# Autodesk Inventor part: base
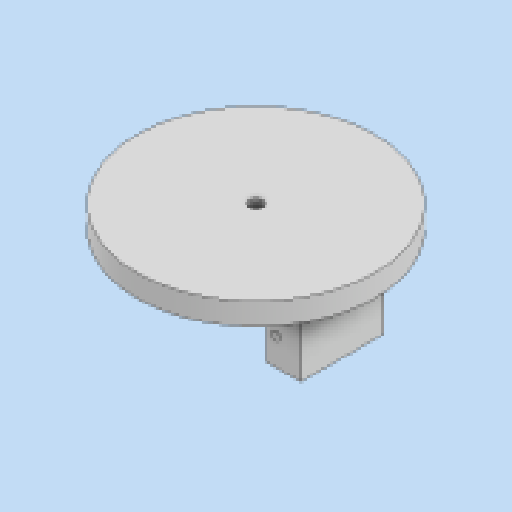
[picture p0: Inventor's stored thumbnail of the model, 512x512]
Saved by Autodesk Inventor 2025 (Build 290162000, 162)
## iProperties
Created: 2026-03
Part Number: base
Material: Generico
Document SubType Name: Modeling
Designer: Ryzen5700u
Density: 1 g/cm^3
Appearance: Default
Author: Ryzen5700u
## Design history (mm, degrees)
sketch "Schizzo1"
  geometry: L1 (11.5, -6.25)-(11.5, 6.25) reference; L2 (11.5, -6.25)-(16.1, -6.25) reference; L3 (16.1, -6.25)-(16.1, -0.6) reference; L4 (16.1, -0.6)-(14.7, -0.6) reference; L5 (14.7, 0.6)-(16.1, 0.6) reference; L6 (16.1, 0.6)-(16.1, 6.25) reference; L7 (11.5, 6.25)-(16.1, 6.25) reference; L8 (-11.5, 6.25)-(-11.5, -6.25) reference; L9 (-11.5, 6.25)-(-16.1, 6.25) reference; L10 (-16.1, 6.25)-(-16.1, 0.6) reference; L11 (-16.1, 0.6)-(-14.7, 0.6) reference; L12 (-14.7, -0.6)-(-16.1, -0.6) reference; L13 (-16.1, -0.6)-(-16.1, -6.25) reference; L14 (-11.5, -6.25)-(-16.1, -6.25) reference; L15 (11.5, -6.25)-(19.5, -6.25); L16 (19.5, -6.25)-(19.5, 6.25); L17 (19.5, 6.25)-(11.5, 6.25); L18 (11.5, 6.25)-(11.5, -6.25); L19 (-11.5, -6.25)-(-19.5, -6.25); L20 (-19.5, -6.25)-(-19.5, 6.25); L21 (-19.5, 6.25)-(-11.5, 6.25); L22 (-11.5, 6.25)-(-11.5, -6.25); C1 r 1 at (13.9, 0); A1 r 1 centre (13.9, 0) between (14.7, 0.6) and (14.7, -0.6) reference; A2 r 1 centre (-13.9, 0) between (-14.7, -0.6) and (-14.7, 0.6) reference; 9 further points
  constraints: 16 end point, 4 parallel, 2 coincident, 2 horizontal, 2 perpendicular, 1 centre point, 1 point on line, 3 other
  dimensions: "d0" = 8 distance of L17.end L16.end; "d1" = 8 distance of L20.end L21.end
  node "Riferimento1"
  node "Riferimento2"
node "Piano di lavoro1"
extrude "Estrusione1" new body sketch "Schizzo1" stored distance "d2" = 10; taper "d3" = 0 deg
sketch "Schizzo2"
  geometry: L1 (0, -18.7)-(8, -18.7) reference; L2 (8, 0)-(8, -18.7) reference; L3 (8, 0)-(0, 0) reference; L4 (0, 0)-(0, -18.7) reference; L5 (-31, -18.7)-(-23, -18.7) reference; L6 (-23, 0)-(-23, -18.7) reference; L7 (-23, 0)-(-31, 0) reference; L8 (-31, 0)-(-31, -18.7) reference; 1 further point
extrude "Estrusione2" join sketch "Schizzo2" distance "d4" = 3; taper "d5" = 0 deg
sketch "Schizzo3"
  geometry: L1 (0, 0)-(0, -18.7) reference; L2 (0, -9.35)-(-23, -9.35); L3 (-23, 0)-(-23, -18.7) reference; L4 (8.625, 8.65)-(-31.625, 8.65); A1 r 27 centre (-11.5, -9.35) between (8.625, 8.65) and (-31.625, 8.65); 1 further point
  constraints: 4 end point, 3 midpoint, 2 point on circle, 1 centre point, 1 horizontal
  dimensions: "d6" = 54 diameter of A1; "d7" = 18 distance between parallel lines of L4 L2
extrude "Estrusione3" join sketch "Schizzo3" distance "d8" = 5; taper "d9" = 0 deg
sketch "Schizzo4"
  geometry: L1 (-11.5, -9.35)-(-19.5, -9.35) reference; L2 (-19.5, -9.35)-(-19.5, 9.35) reference; L3 (-19.5, 9.35)-(-11.5, 9.35) reference; L4 (-11.5, 9.35)-(-11.5, -9.35) reference; L5 (11.5, -9.35)-(11.5, 9.35) reference; L6 (11.5, 9.35)-(19.5, 9.35) reference; L7 (19.5, 9.35)-(19.5, -9.35) reference; L8 (19.5, -9.35)-(11.5, -9.35) reference; L9 (-11.5, 9.35)-(11.5, 9.35); L10 (11.5, 9.35)-(11.5, -9.35); L11 (11.5, -9.35)-(-11.5, -9.35); L12 (-11.5, -9.35)-(-11.5, 9.35); C1 r 27 at (0, 0) reference; 3 further points
  constraints: 8 end point, 2 parallel, 1 horizontal, 1 perpendicular
extrude "Estrusione4" join sketch "Schizzo4" distance "d10" = 2.9; taper "d11" = 0 deg
sketch "Schizzo5"
  geometry: C1 r 2.2 at (0, 0) reference; 1 further point
hole "Foro1" sketch "Schizzo5" at (0, 0) diameter "d13" = 2.9; stored, may be unused: countersink angle "d17" = 90 deg, drill point angle "d19" = 118 deg; dims "d14" = 6, "d15" = 5, "d16" = 5, "d18" = 8
chamfer "Smusso1" distance "d20" = 3; stored, may be unused: second distance "d21" = 2, angle "d22" = 45 deg
node "Piano di lavoro2"
sketch "Schizzo6"
  geometry: L1 (0, 12.707)-(11.718, 12.707); L2 (11.718, 12.707)-(11.718, 20.126); L3 (11.718, 20.126)-(0, 20.126); L4 (0, 20.126)-(0, 12.707); 1 further point
  constraints: 8 end point, 2 parallel, 1 horizontal, 1 perpendicular
extrude "Estrusione5" cut sketch "Schizzo6" stored distance "d23" = 10; taper "d24" = 0 deg
chamfer "Smusso2" distance "d25" = 2.9; stored, may be unused: second distance "d26" = 2, angle "d27" = 45 deg
node "Solido1"
node "Linea chiusa proiettata1"
node "Linea chiusa proiettata2"
node "Linea chiusa proiettata3"
node "Riferimento3"
